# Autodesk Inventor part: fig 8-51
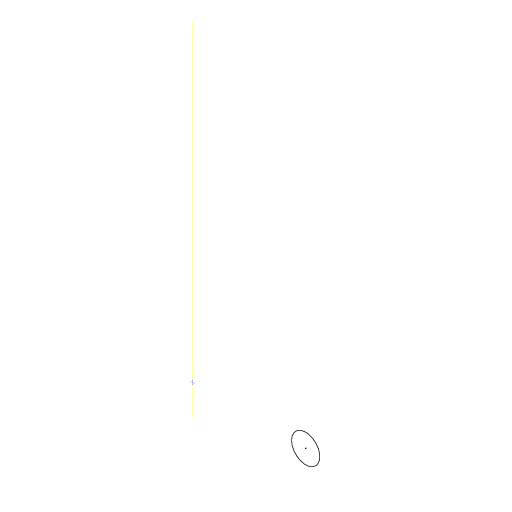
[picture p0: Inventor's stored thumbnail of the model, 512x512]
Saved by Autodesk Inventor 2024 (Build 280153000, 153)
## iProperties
Shininess: 77.0
Length Units: 11269
Angle Units: 11279
Time Units: 11290
Mass Units: 11283
Length Display Precision: 3
Angle Display Precision: 2
Created: 2002-01
Part Number: fig 8-51
Document SubType Name: Modeling
Designer: CADSoft
Density: 1 g/cm^3
Material: Generic
Appearance: Default
Density: 0.0
Volumn: 0.0
Area: 0.0
PropertySet Name: Model Information
Control State: 0
Master: False
Checked Out: False
Author: CADSoft
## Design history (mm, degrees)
sketch "Sketch2"
  geometry: C1 r 2.5 at (-20, -0.092); 1 further point
  constraints: 1 centre point, 2 other
workaxis "Work Axis1"
body "Solid1"
